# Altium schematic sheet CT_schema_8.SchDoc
size 250 x 169 mm
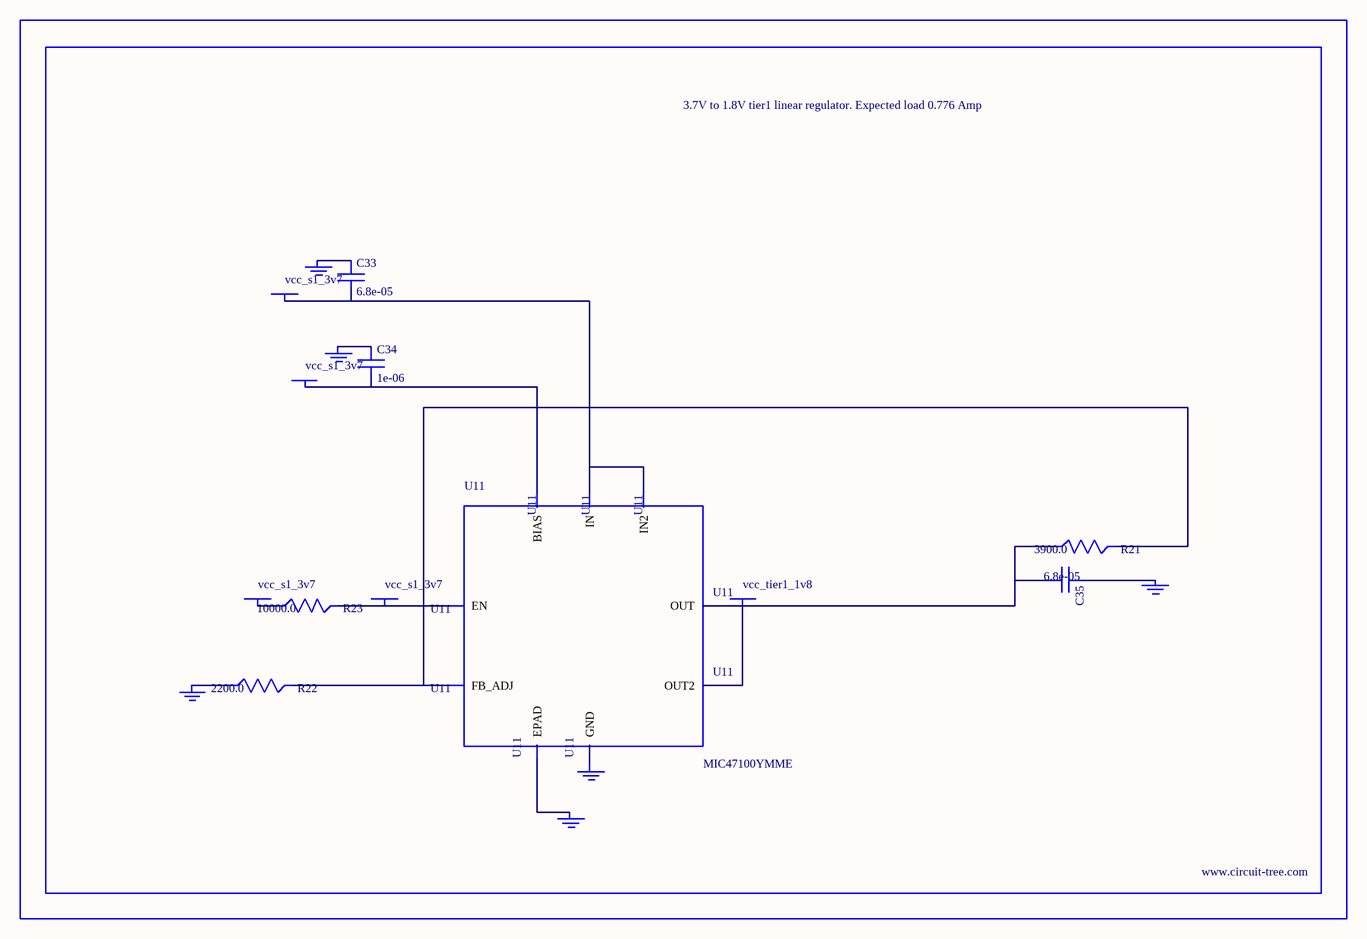
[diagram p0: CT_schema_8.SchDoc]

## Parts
BORDER7  (no value)
C33  6.8e-05  [2220]
C34  1e-06  [C0603]
C35  6.8e-05  [2220]
GND_INSTANCE_7_0  (no value)
GND_INSTANCE_7_1  (no value)
GND_INSTANCE_7_2  (no value)
GND_INSTANCE_7_3  (no value)
GND_INSTANCE_7_4  (no value)
GND_INSTANCE_7_5  (no value)
POWER_INSTANCE_7_0  vcc_s1_3v7
POWER_INSTANCE_7_1  vcc_s1_3v7
POWER_INSTANCE_7_2  vcc_s1_3v7
POWER_INSTANCE_7_3  vcc_s1_3v7
POWER_INSTANCE_7_4  vcc_tier1_1v8
R21  3900.0  [R0603]
R22  2200.0  [R0603]
R23  10000.0  [R0603]
U11  MIC47100YMME  [MSOP-8_EP]

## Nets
NetC33_1: C33.1 GND_INSTANCE_7_0.0(GND)
NetC33_2: C33.2 POWER_INSTANCE_7_0.0(PWR) U11.1(IN) U11.2(IN2)
NetC34_1: C34.1 GND_INSTANCE_7_1.0(GND)
NetC34_2: C34.2 POWER_INSTANCE_7_1.0(PWR) U11.4(BIAS)
NetC35_1: C35.1 GND_INSTANCE_7_3.0(GND)
NetC35_2: C35.2 POWER_INSTANCE_7_4.0(PWR) R21.1 U11.7(OUT) U11.8(OUT2)
NetGND_INSTANCE_7_2_0: GND_INSTANCE_7_2.0(GND) R22.1
NetGND_INSTANCE_7_4_0: GND_INSTANCE_7_4.0(GND) U11.EPAD
NetGND_INSTANCE_7_5_0: GND_INSTANCE_7_5.0(GND) U11.3(GND)
NetPOWER_INSTANCE_7_2_0: POWER_INSTANCE_7_2.0(PWR) R23.1
NetPOWER_INSTANCE_7_3_0: POWER_INSTANCE_7_3.0(PWR) R23.2 U11.5(EN)
NetR21_2: R21.2 R22.2 U11.6(FB_ADJ)

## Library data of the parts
BORDER7 = BORDER_PAGE7
C33 C35 = C5750X5R1A686M
C34 = C0603C105K3RACTU
GND_INSTANCE_7_0-GND_INSTANCE_7_5 = GND
POWER_INSTANCE_7_0-POWER_INSTANCE_7_4 = PWR
R21 = RC0603JR-073K9L
R22 = RC0603JR-072K2L
R23 = RC0603JR-0710KL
